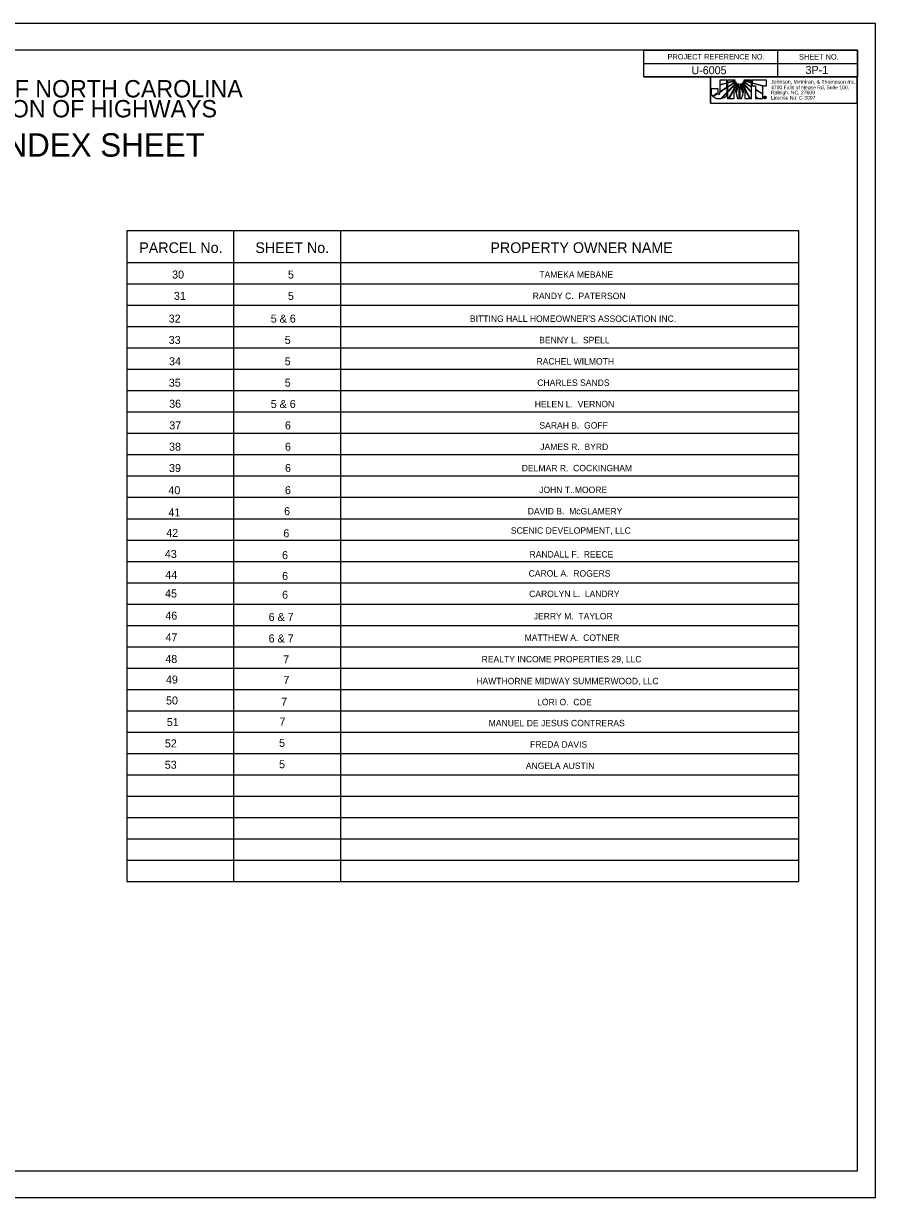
# Model space of a CAD drawing. Extents: x 811276 to 1773517, y 644924 to 886726.
# Drawn here: x 812162 to 812960, y 644924 to 646024 of the extents above; entities that cross this region are included whole.
import ezdxf

# ---------------------------------------------------------------- set-up
doc = ezdxf.new("R2010")
doc.units = 0
for name, color, linetype in [('Default', 7, 'Continuous'), ('Old_Level_2', 7, 'Continuous'), ('Prop PHM Black Shape', 7, 'Continuous'), ('Sheet Data Field CELL', 7, 'Continuous'), ('Sheet Plot Border Outside CELL', 7, 'Continuous'), ('Sheet Summary CELL', 7, 'Continuous')]:
    doc.layers.add(name, color=color, linetype=linetype)

msp = doc.modelspace()

# ---------------------------------------------------------------- linework, layer by layer
at = {"layer": 'Default'}
for p, q in [((812820.5, 645971.4), (812814, 645971.4)), ((812814, 645971.4), (812814, 645967.2)), ((812814, 645967.2), (812820.5, 645969)), ((812820.5, 645968.5), (812814, 645966.7)), ((812814, 645966.7), (812814, 645960.7)), ((812814, 645960.7), (812820.5, 645964.8)), ((812820.5, 645969), (812820.5, 645971.4)), ((812820.5, 645964.8), (812820.5, 645968.5)), ((812828.4, 645971.5), (812821.1, 645971.5)), ((812821.1, 645971.5), (812821.1, 645969.2)), ((812821.1, 645969.2), (812826.5, 645970.7)), ((812826.5, 645970.2), (812821.1, 645968.7)), ((812821.1, 645968.7), (812821.1, 645965.2)), ((812821.1, 645965.2), (812826, 645968.2)), ((812826.7, 645968.2), (812821.1, 645964.6)), ((812821.1, 645960.6), (812827.9, 645967.7)), ((812828.2, 645967.3), (812821.1, 645959.9)), ((812821.1, 645964.6), (812821.1, 645960.6)), ((812826, 645968.2), (812828.6, 645970.4)), ((812826.5, 645970.7), (812828.4, 645971.5)), ((812828.6, 645970.4), (812826.5, 645970.2)), ((812829.2, 645969.4), (812826.7, 645968.2)), ((812827.5, 645963.6), (812827.5, 645965.3)), ((812827.5, 645965.3), (812827.8, 645964.1)), ((812827.8, 645964.1), (812829.1, 645966.6)), ((812827.9, 645967.7), (812829.2, 645969.4)), ((812829.6, 645966.4), (812828, 645963.5)), ((812829.9, 645968.6), (812828.2, 645967.3)), ((812829, 645959.7), (812830.6, 645966.1)), ((812829.1, 645966.6), (812829.9, 645968.6)), ((812831, 645965.7), (812829.2, 645958.8)), ((812830.8, 645968.1), (812829.6, 645966.4)), ((812830.6, 645966.1), (812830.8, 645968.1)), ((812831.9, 645967.8), (812831, 645965.7)), ((812832.2, 645962.7), (812831.9, 645967.8)), ((812833, 645967.8), (812832.6, 645962.7)), ((812833.8, 645965.7), (812833, 645967.8)), ((812835.7, 645958.7), (812833.8, 645965.7)), ((812834, 645968.1), (812834.2, 645966)), ((812835.2, 645966.4), (812834, 645968.1)), ((812834.2, 645966), (812835.9, 645959.5)), ((812834.9, 645968.6), (812835.7, 645966.6)), ((812836.6, 645967.3), (812834.9, 645968.6)), ((812836.9, 645963.4), (812835.2, 645966.4)), ((812835.6, 645969.4), (812836.9, 645967.6)), ((812838.1, 645968.2), (812835.6, 645969.4)), ((812835.7, 645966.6), (812837.1, 645964)), ((812836.2, 645970.4), (812838.9, 645968.2)), ((812838.2, 645970.2), (812836.2, 645970.4)), ((812843.7, 645971.4), (812836.6, 645971.5)), ((812836.6, 645971.5), (812838.4, 645970.6)), ((812843.7, 645959.9), (812836.6, 645967.3)), ((812836.9, 645967.6), (812843.7, 645960.5)), ((812837.1, 645964), (812837.4, 645965.3)), ((812837.4, 645965.3), (812837.4, 645963.4)), ((812843.7, 645964.7), (812838.1, 645968.2)), ((812843.7, 645968.6), (812838.2, 645970.2)), ((812838.4, 645970.6), (812843.7, 645969.1)), ((812838.9, 645968.2), (812843.7, 645965.2)), ((812843.7, 645969.1), (812843.7, 645971.4)), ((812843.7, 645965.2), (812843.7, 645968.6)), ((812843.7, 645960.5), (812843.7, 645964.7)), ((812857.7, 645971.5), (812844.2, 645971.5)), ((812844.2, 645971.5), (812844.2, 645969)), ((812844.2, 645969), (812844.2, 645968.9)), ((812844.2, 645968.9), (812854.9, 645965.9)), ((812844.2, 645968.5), (812844.2, 645968.5)), ((812844.2, 645968.5), (812844.2, 645965.9)), ((812854.2, 645965.7), (812844.2, 645968.5)), ((812844.2, 645965.9), (812847.5, 645965.9)), ((812847.5, 645965.9), (812847.5, 645962.8)), ((812854.2, 645958.6), (812854.2, 645965.7)), ((812854.9, 645965.9), (812857.7, 645965.9)), ((812857.7, 645965.9), (812857.7, 645971.5)), ((812821.1, 645959.9), (812821.1, 645954.1)), ((812821.1, 645954.1), (812822.2, 645954.1)), ((812822.2, 645954.1), (812827.5, 645963.6)), ((812827.5, 645962.7), (812822.7, 645954.1)), ((812822.7, 645954.1), (812827.5, 645954.1)), ((812827.5, 645954.1), (812827.5, 645962.7)), ((812828, 645963.5), (812829, 645959.7)), ((812829.2, 645958.8), (812830.4, 645954.1)), ((812830.4, 645954.1), (812832.2, 645954.1)), ((812832.2, 645954.1), (812832.2, 645962.7)), ((812832.6, 645962.7), (812832.6, 645954.1)), ((812832.6, 645954.1), (812834.4, 645954.1)), ((812834.4, 645954.1), (812835.7, 645958.7)), ((812835.9, 645959.5), (812836.9, 645963.4)), ((812837.4, 645963.4), (812842.5, 645954.1)), ((812842, 645954.1), (812837.4, 645962.5)), ((812837.4, 645962.5), (812837.4, 645954.1)), ((812837.4, 645954.1), (812842, 645954.1)), ((812842.5, 645954.1), (812843.7, 645954.1)), ((812843.7, 645954.1), (812843.7, 645959.9)), ((812847.5, 645962.8), (812854.2, 645958.6)), ((812847.5, 645962.3), (812847.5, 645956.5)), ((812854.2, 645958.1), (812847.5, 645962.3)), ((812847.5, 645956.5), (812849.8, 645954.1)), ((812849.2, 645954.1), (812847.5, 645955.9)), ((812847.5, 645955.9), (812847.5, 645954.1)), ((812847.5, 645954.1), (812849.2, 645954.1)), ((812849.8, 645954.1), (812854.2, 645954.1)), ((812854.2, 645954.1), (812854.2, 645958.1)), ((812855.9, 645954.7), (812855.9, 645955.7)), ((812855.9, 645955.7), (812856.3, 645955.7)), ((812856.1, 645954.7), (812855.9, 645954.7)), ((812856.3, 645955.5), (812856.1, 645955.5)), ((812856.1, 645955.5), (812856.1, 645955.3)), ((812856.1, 645955.3), (812856.3, 645955.3)), ((812856.3, 645955.1), (812856.1, 645955.1)), ((812856.1, 645955.1), (812856.1, 645954.7)), ((812856.3, 645956.3), (812856.3, 645956.1)), ((812856.3, 645956.1), (812856.3, 645956.3)), ((812856.3, 645955.7), (812856.3, 645955.5)), ((812856.3, 645955.5), (812856.3, 645955.7)), ((812856.3, 645955.7), (812856.3, 645955.7)), ((812856.3, 645955.5), (812856.3, 645955.5)), ((812856.3, 645955.3), (812856.3, 645955.1)), ((812856.3, 645955.1), (812856.3, 645955.3)), ((812856.3, 645955.3), (812856.3, 645955.3)), ((812856.3, 645955.1), (812856.3, 645955.1)), ((812856.3, 645954.3), (812856.3, 645954.1)), ((812856.3, 645954.1), (812856.3, 645954.3)), ((812856.3, 645954.3), (812856.3, 645954.3)), ((812856.3, 645954.1), (812856.3, 645954.1))]:
    msp.add_line(p, q, dxfattribs=at)
for points in [[(812805.3, 645949.7), (812942.8, 645949.6), (812942.8, 645974.4), (812805.3, 645974.5)], [(812821.1, 645954.1), (812821.1, 645959.9), (812828.2, 645967.3), (812829.9, 645968.6), (812829.3, 645967), (812827.8, 645964.1), (812827.5, 645965.3), (812827.5, 645963.6), (812822.2, 645954.1)], [(812836.6, 645971.5), (812843.7, 645971.4), (812843.7, 645969.1), (812838.4, 645970.6)]]:
    msp.add_lwpolyline(points, close=True, dxfattribs=at)
for points in [[(812814, 645967.2), (812820.5, 645969), (812820.5, 645971.4), (812814, 645971.4), (812814, 645967.2)], [(812814, 645960.7), (812820.5, 645964.8), (812820.5, 645968.5), (812814, 645966.7), (812814, 645960.7)], [(812826.5, 645970.7), (812828.4, 645971.5), (812821.1, 645971.5), (812821.1, 645969.2), (812826.5, 645970.7)], [(812821.1, 645968.7), (812821.1, 645965.2), (812826, 645968.2), (812828.6, 645970.4), (812826.5, 645970.2), (812821.1, 645968.7)], [(812821.1, 645964.6), (812821.1, 645960.6), (812827.9, 645967.7), (812829.2, 645969.4), (812826.7, 645968.2), (812821.1, 645964.6)], [(812829.9, 645968.6), (812828.2, 645967.3), (812821.1, 645959.9), (812821.1, 645954.1), (812822.2, 645954.1), (812827.5, 645963.6), (812827.5, 645965.3), (812827.8, 645964.1), (812829.1, 645966.6), (812829.9, 645968.6)], [(812830.8, 645968.1), (812829.6, 645966.4), (812828, 645963.5), (812829, 645959.7), (812830.6, 645966.1), (812830.8, 645968.1)], [(812831, 645965.7), (812829.2, 645958.8), (812830.4, 645954.1), (812832.2, 645954.1), (812832.2, 645962.7), (812831.9, 645967.8), (812831, 645965.7)], [(812833, 645967.8), (812832.6, 645962.7), (812832.6, 645954.1), (812834.4, 645954.1), (812835.7, 645958.7), (812833.8, 645965.7), (812833, 645967.8)], [(812834, 645968.1), (812834.2, 645966), (812835.9, 645959.5), (812836.9, 645963.4), (812835.2, 645966.4), (812834, 645968.1)], [(812834.9, 645968.6), (812835.7, 645966.6), (812837.1, 645964), (812837.4, 645965.3), (812837.4, 645963.4), (812842.5, 645954.1), (812843.7, 645954.1), (812843.7, 645959.9), (812836.6, 645967.3), (812834.9, 645968.6)], [(812835.6, 645969.4), (812836.9, 645967.6), (812843.7, 645960.5), (812843.7, 645964.7), (812838.1, 645968.2), (812835.6, 645969.4)], [(812836.2, 645970.4), (812838.9, 645968.2), (812843.7, 645965.2), (812843.7, 645968.6), (812838.2, 645970.2), (812836.2, 645970.4)], [(812838.4, 645970.6), (812843.7, 645969.1), (812843.7, 645971.4), (812836.6, 645971.5), (812838.4, 645970.6)], [(812857.7, 645971.5), (812844.2, 645971.5), (812844.2, 645969), (812844.2, 645968.9), (812854.9, 645965.9), (812857.7, 645965.9), (812857.7, 645971.5)], [(812844.2, 645968.5), (812844.2, 645968.5), (812844.2, 645965.9), (812847.5, 645965.9), (812847.5, 645962.8), (812854.2, 645958.6), (812854.2, 645965.7), (812844.2, 645968.5)], [(812822.7, 645954.1), (812827.5, 645954.1), (812827.5, 645962.7), (812822.7, 645954.1)], [(812837.4, 645954.1), (812842, 645954.1), (812837.4, 645962.5), (812837.4, 645954.1)], [(812847.5, 645962.3), (812847.5, 645956.5), (812849.8, 645954.1), (812854.2, 645954.1), (812854.2, 645958.1), (812847.5, 645962.3), (812847.5, 645962.3)], [(812847.5, 645954.1), (812847.5, 645954.1), (812849.2, 645954.1), (812847.5, 645955.9), (812847.5, 645954.1)], [(812856.7, 645954.9), (812856.7, 645954.9), (812856.7, 645954.9), (812856.7, 645954.8), (812856.7, 645954.7), (812856.5, 645954.7)]]:
    msp.add_lwpolyline(points, dxfattribs=at)
for points, degree in [([(812813.1, 645958.1), (812812.7, 645958.1), (812812.4, 645958.3), (812812.3, 645959), (812812.3, 645959), (812807.6, 645956.1), (812807.6, 645956.1), (812809.1, 645954.6), (812811.3, 645953.8), (812813.3, 645953.8), (812813.8, 645953.8), (812814.1, 645953.8), (812814.7, 645953.9), (812814.7, 645953.9), (812820.5, 645959.9), (812820.5, 645959.9), (812820.5, 645959.9), (812820.5, 645964.2), (812820.5, 645964.2), (812820.5, 645964.2), (812814, 645960.1), (812814, 645960.1), (812814, 645958.5), (812813.6, 645958.1), (812813.1, 645958.1)], 3), ([(812813.1, 645958.1), (812812.7, 645958.1), (812812.4, 645958.3), (812812.3, 645959), (812812.3, 645959), (812807.6, 645956.1), (812807.6, 645956.1), (812809.1, 645954.6), (812811.3, 645953.8), (812813.3, 645953.8), (812813.8, 645953.8), (812814.1, 645953.8), (812814.7, 645953.9), (812814.7, 645953.9), (812820.5, 645959.9), (812820.5, 645959.9), (812820.5, 645959.9), (812820.5, 645964.2), (812820.5, 645964.2), (812820.5, 645964.2), (812814, 645960.1), (812814, 645960.1), (812814, 645958.5), (812813.6, 645958.1), (812813.1, 645958.1)], 3), ([(812812.2, 645963.4), (812812.2, 645963.4), (812806.2, 645963.4), (812806.2, 645963.4), (812806.2, 645963.4), (812806.2, 645959.7), (812806.2, 645959.7), (812806.2, 645959.7), (812806.2, 645959.3), (812806.2, 645959.3), (812806.2, 645958.1), (812806.6, 645957.2), (812807.3, 645956.5), (812807.3, 645956.5), (812812.2, 645959.4), (812812.2, 645959.5), (812812.2, 645959.5), (812812.2, 645963.4), (812812.2, 645963.4)], 3), ([(812820.5, 645959.2), (812820.5, 645959.2), (812815.5, 645954), (812815.5, 645954), (812817.9, 645954.6), (812820.3, 645956.3), (812820.5, 645959.2)], 3), ([(812856.3, 645954.1), (812856, 645954.1), (812855.7, 645954.2), (812855.5, 645954.4), (812855.3, 645954.6), (812855.2, 645954.9), (812855.2, 645955.2), (812855.2, 645955.5), (812855.3, 645955.8), (812855.5, 645956), (812855.7, 645956.2), (812856, 645956.3), (812856.3, 645956.3)], 3), ([(812856.3, 645956.1), (812856, 645956.1), (812855.8, 645956), (812855.7, 645955.8), (812855.5, 645955.7), (812855.4, 645955.4), (812855.4, 645955.2), (812855.4, 645955), (812855.5, 645954.7), (812855.7, 645954.6), (812855.8, 645954.4), (812856, 645954.3), (812856.3, 645954.3)], 3), ([(812856.3, 645956.3), (812856.6, 645956.3), (812856.8, 645956.2), (812857.1, 645956), (812857.3, 645955.8), (812857.4, 645955.5), (812857.4, 645955.2)], 3), ([(812856.3, 645954.3), (812856.5, 645954.3), (812856.7, 645954.4), (812856.9, 645954.6), (812857.1, 645954.7), (812857.2, 645955), (812857.2, 645955.2), (812857.2, 645955.4), (812857.1, 645955.7), (812856.9, 645955.8), (812856.7, 645956), (812856.5, 645956.1), (812856.3, 645956.1)], 3), ([(812856.3, 645955.7), (812856.6, 645955.7), (812856.7, 645955.6), (812856.7, 645955.4), (812856.7, 645955.3), (812856.7, 645955.2), (812856.6, 645955.2)], 3), ([(812856.3, 645955.3), (812856.4, 645955.3), (812856.5, 645955.3), (812856.5, 645955.4), (812856.5, 645955.5), (812856.4, 645955.5), (812856.3, 645955.5)], 3), ([(812857.4, 645955.2), (812857.4, 645954.9), (812857.3, 645954.6), (812857.1, 645954.4), (812856.9, 645954.2), (812856.6, 645954.1), (812856.3, 645954.1)], 3), ([(812856.5, 645955.1), (812856.4, 645955.1), (812856.4, 645955.1), (812856.3, 645955.1)], 2), ([(812856.5, 645954.7), (812856.5, 645954.8), (812856.5, 645954.8), (812856.5, 645954.9), (812856.5, 645955), (812856.5, 645955), (812856.5, 645955.1)], 3), ([(812856.6, 645955.2), (812856.7, 645955.1), (812856.7, 645955.1), (812856.7, 645954.9)], 2)]:
    msp.add_open_spline(points, degree=degree, dxfattribs=at)
at = {"layer": 'Prop PHM Black Shape'}
msp.add_lwpolyline([(812805.3, 645974.5), (812942.8, 645974.4), (812942.8, 645949.6), (812805.3, 645949.7)], close=True, dxfattribs=at)
at = {"layer": 'Sheet Plot Border Outside CELL'}
msp.add_lwpolyline([(812959.9, 646024.5), (811275.9, 646024.5), (811275.9, 644924.5), (812959.9, 644924.5)], close=True, dxfattribs=at)
at = {"layer": 'Sheet Summary CELL'}
for p, q in [((812867.9, 645999.4), (812867.9, 645974.4)), ((812742.8, 645986.9), (812942.9, 645986.9)), ((812742.8, 645974.4), (812942.9, 645974.4)), ((812192.5, 645910.7), (812192.5, 645910.7)), ((812258.4, 645830.5), (812887.8, 645830.5)), ((812258.4, 645830.5), (812258.4, 645220.5)), ((812358.4, 645830.5), (812358.4, 645220.5)), ((812458.4, 645830.5), (812458.4, 645220.5)), ((812887.8, 645830.5), (812887.8, 645220.5)), ((812258.4, 645800.5), (812887.8, 645800.5)), ((812258.4, 645780.5), (812887.8, 645780.5)), ((812258.4, 645760.5), (812887.8, 645760.5)), ((812258.4, 645740.5), (812887.8, 645740.5)), ((812258.4, 645720.5), (812887.8, 645720.5)), ((812258.4, 645700.5), (812887.8, 645700.5)), ((812258.4, 645680.5), (812887.8, 645680.5)), ((812258.4, 645660.5), (812887.8, 645660.5)), ((812258.4, 645640.5), (812887.8, 645640.5)), ((812258.4, 645620.5), (812887.8, 645620.5)), ((812258.4, 645600.5), (812887.8, 645600.5)), ((812258.4, 645580.5), (812887.8, 645580.5)), ((812258.4, 645560.5), (812887.8, 645560.5)), ((812258.4, 645540.5), (812887.8, 645540.5)), ((812258.4, 645520.5), (812887.8, 645520.5)), ((812258.4, 645500.5), (812887.8, 645500.5)), ((812258.4, 645480.5), (812887.8, 645480.5)), ((812258.4, 645460.5), (812887.8, 645460.5)), ((812258.4, 645440.5), (812887.8, 645440.5)), ((812258.4, 645420.5), (812887.8, 645420.5)), ((812258.4, 645400.5), (812887.8, 645400.5)), ((812258.4, 645380.5), (812887.8, 645380.5)), ((812258.4, 645360.5), (812887.8, 645360.5)), ((812258.4, 645340.5), (812887.8, 645340.5)), ((812258.4, 645320.5), (812887.8, 645320.5)), ((812258.4, 645300.5), (812887.8, 645300.5)), ((812258.4, 645280.5), (812887.8, 645280.5)), ((812258.4, 645260.5), (812887.8, 645260.5)), ((812258.4, 645240.5), (812887.8, 645240.5)), ((812258.4, 645220.5), (812887.8, 645220.5))]:
    msp.add_line(p, q, dxfattribs=at)
for points in [[(812942.9, 645999.5), (811442.9, 645999.5), (811442.9, 644949.5), (812942.9, 644949.5)], [(812742.8, 645999.5), (812942.9, 645999.5), (812942.9, 645974.4), (812742.8, 645974.4)]]:
    msp.add_lwpolyline(points, close=True, dxfattribs=at)

# ---------------------------------------------------------------- texts
at = {"layer": 'Default'}
for s, height, p in [('Johnson, Mirmiran, & Thompson Inc.', 3.514, (812862, 645968.1)), ('4700 Falls of Neuse Rd, Suite 100, ', 3.414, (812862, 645962.9)), ('Raleigh, NC, 27609', 3.414, (812861.9, 645958.1)), ('License No: C-3097', 3.414, (812861.9, 645953.2))]:
    msp.add_text(s, height=height, rotation=359.9675, dxfattribs=at).set_placement(p)
for s, p in [('PARCEL No.', (812270, 645809.4)), ('SHEET No.', (812378.8, 645809.4)), ('PROPERTY OWNER NAME', (812599, 645809.4))]:
    msp.add_text(s, height=10, dxfattribs=at).set_placement(p)
at = {"layer": 'Old_Level_2'}
for s, height, p in [('30', 7.5, (812300.8, 645785.5)), ('5', 7.5, (812409.3, 645785.5)), ('TAMEKA MEBANE', 6, (812644.9, 645786.2)), ('31', 7.5, (812302.5, 645765.5)), ('5', 7.5, (812409.3, 645765.5)), ('RANDY C.  PATERSON', 6, (812638.7, 645766.2)), ('32', 7.5, (812297.6, 645744.2)), ('5 & 6', 7.5, (812393.2, 645744.2)), ("BITTING HALL HOMEOWNER'S ASSOCIATION INC.", 6, (812579.8, 645744.9)), ('33', 7.5, (812297.6, 645724.2)), ('5', 7.5, (812406.3, 645724.2)), ('BENNY L.  SPELL', 6, (812644.7, 645724.9)), ('34', 7.5, (812297.9, 645704.2)), ('5', 7.5, (812406.3, 645704.2)), ('RACHEL WILMOTH', 6, (812642.2, 645704.9)), ('35', 7.5, (812297.7, 645684.2)), ('5', 7.5, (812406.3, 645684.2)), ('CHARLES SANDS', 6, (812642.9, 645684.9)), ('5 & 6', 7.5, (812393.2, 645664.2)), ('HELEN L.  VERNON', 6, (812640.6, 645664.9)), ('37', 7.5, (812298.1, 645644.2)), ('6', 7.5, (812406.5, 645644.2)), ('SARAH B.  GOFF', 6, (812644.9, 645644.9)), ('38', 7.5, (812297.9, 645624.2)), ('6', 7.5, (812406.5, 645624.2)), ('JAMES R.  BYRD', 6, (812645.7, 645624.9)), ('39 ', 7.5, (812297.9, 645604.2)), ('6', 7.5, (812406.5, 645604.2)), ('DELMAR R.  COCKINGHAM', 6, (812628.4, 645604.9)), ('40  ', 7.5, (812297.3, 645583.4)), ('6', 7.5, (812406.5, 645583.4)), ('JOHN T..MOORE', 6, (812644.7, 645584.5)), ('41', 7.5, (812297.3, 645562.6)), ('6', 7.5, (812405.7, 645563.8)), ('DAVID B.  McGLAMERY', 6, (812634, 645564.5)), ('42  ', 7.5, (812295.3, 645543.4)), ('6', 7.5, (812405, 645543)), ('SCENIC DEVELOPMENT, LLC', 6, (812618.2, 645546.4)), ('43', 7.5, (812294, 645523.7)), ('6', 7.5, (812403.8, 645522.6)), ('RANDALL F.  REECE', 6, (812635.7, 645524.1)), ('44', 7.5, (812294.4, 645504.1)), ('6', 7.5, (812403.8, 645503)), ('CAROL A.  ROGERS', 6, (812634.8, 645506.2)), ('45  ', 7.5, (812294.2, 645486.7)), ('6', 7.5, (812403.8, 645485.5)), ('CAROLYN L.  LANDRY', 6, (812635.3, 645487)), ('46', 7.5, (812294.4, 645465.9)), ('6 & 7', 7.5, (812391.2, 645464.7)), ('JERRY M.  TAYLOR', 6, (812639.6, 645466.2)), ('47 ', 7.5, (812294.6, 645445.6)), ('6 & 7', 7.5, (812391.2, 645444.5)), ('MATTHEW A.  COTNER', 6, (812631.1, 645446)), ('48 ', 7.5, (812294.4, 645425.3)), ('7', 7.5, (812404.9, 645424.9)), ('REALTY INCOME PROPERTIES 29, LLC', 6, (812590.8, 645425.9)), ('49 ', 7.5, (812295, 645406)), ('7', 7.5, (812405.1, 645405.7)), ('HAWTHORNE MIDWAY SUMMERWOOD, LLC', 6, (812585.8, 645405.4)), ('50 ', 7.5, (812295.1, 645386.4)), ('7', 7.5, (812403, 645385.3)), ('LORI O.  COE', 6, (812642.8, 645385.7)), ('51', 7.5, (812295.8, 645366.2)), ('7', 7.5, (812401.4, 645366.7)), ('MANUEL DE JESUS CONTRERAS', 6, (812597.4, 645366)), ('52', 7.5, (812294, 645346.2)), ('5', 7.5, (812401, 645346.7)), ('FREDA DAVIS', 6, (812636.2, 645346)), ('53', 7.5, (812293.9, 645326.2)), ('5', 7.5, (812401, 645326.7)), ('ANGELA AUSTIN', 6, (812632.2, 645326))]:
    msp.add_text(s, height=height, dxfattribs=at).set_placement(p)
msp.add_text('36  ', height=7.5, rotation=0.5468, dxfattribs=at).set_placement((812298, 645664.4))
at = {"layer": 'Sheet Data Field CELL'}
for s, p in [('U-6005', (812787.4, 645976.9)), ('3P-1', (812894.3, 645977.2))]:
    msp.add_text(s, height=7.5, dxfattribs=at).set_placement(p)
at = {"layer": 'Sheet Summary CELL'}
for s, height, p in [('PROJECT REFERENCE NO.', 5, (812765, 645990.8)), ('SHEET NO.', 5, (812888.2, 645990.7)), ('STATE OF NORTH CAROLINA', 16.25, (812060.3, 645955.2)), ('DIVISION OF HIGHWAYS', 16.25, (812086.9, 645936.5)), ('PARCEL INDEX SHEET', 21.95, (812010, 645899.7))]:
    msp.add_text(s, height=height, dxfattribs=at).set_placement(p)

doc.saveas('drawing.dxf')
